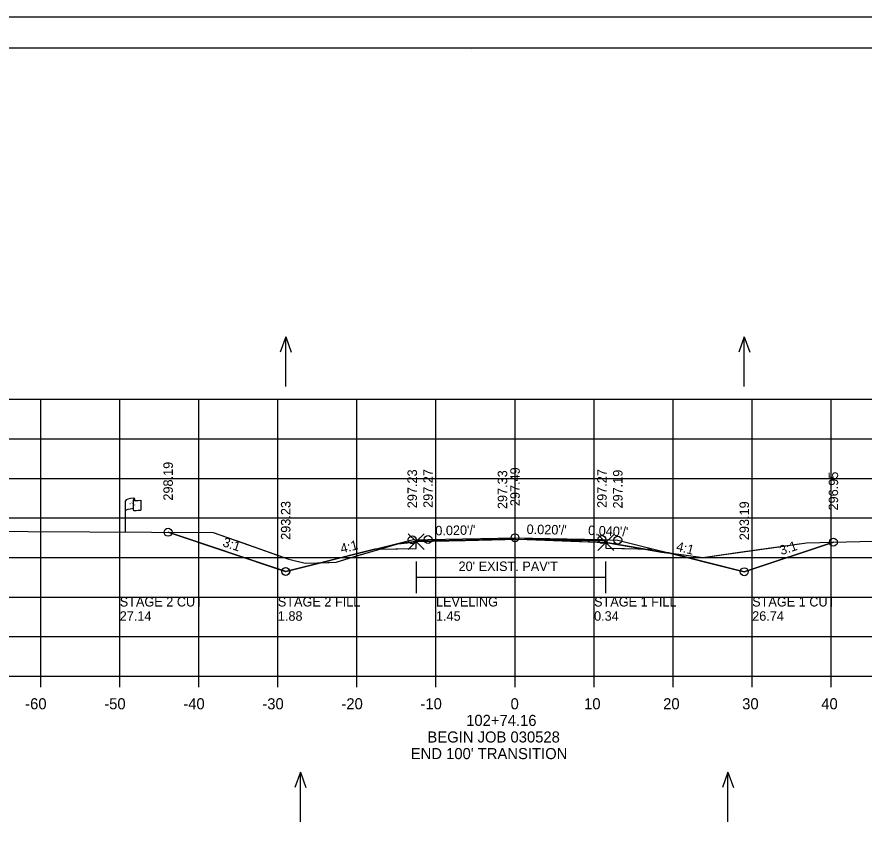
# Model space of a CAD drawing. Extents: x 1370843 to 1371177, y 380307 to 382654.
# Drawn here: x 1370950.7 to 1371057.9, y 380418.2 to 380520.8 of the extents above; entities that cross this region are included whole.
import ezdxf

# ---------------------------------------------------------------- set-up
doc = ezdxf.new("R2010")
doc.units = 0
for name, color, linetype in [('R_Alt Surface', 7, 'Continuous'), ('R_Axis', 7, 'Continuous'), ('R_Axis Annot', 7, 'Continuous'), ('R_Border', 7, 'Continuous'), ('R_Exist Surface', 7, 'Continuous'), ('R_Exist Surface Annot', 7, 'Continuous'), ('R_Fin Surface', 7, 'Continuous'), ('R_Fin Surface Annot', 7, 'Continuous'), ('R_Grid', 7, 'Continuous'), ('R_No Plot', 7, 'Continuous'), ('R_ROW', 7, 'Continuous'), ('R_Water Annot', 7, 'Continuous'), ('R_Xsect Elev', 7, 'Continuous')]:
    doc.layers.add(name, color=color, linetype=linetype)

msp = doc.modelspace()

# ---------------------------------------------------------------- linework, layer by layer
at = {"layer": 'R_Alt Surface'}
msp.add_lwpolyline([(1370996, 380453.5), (1371001.2, 380453.6), (1371001.2, 380454.52), (1371013.71, 380454.77), (1371025.19, 380454.54), (1371025.19, 380453.62), (1371031.25, 380453.5)], dxfattribs=at)
at = {"layer": 'R_Axis'}
for p, q in [((1370868.71, 380437.45), (1371158.71, 380437.45)), ((1370953.71, 380436.05), (1370953.71, 380437.45)), ((1370963.71, 380436.05), (1370963.71, 380437.45)), ((1370973.71, 380436.05), (1370973.71, 380437.45)), ((1370983.71, 380436.05), (1370983.71, 380437.45)), ((1370993.71, 380436.05), (1370993.71, 380437.45)), ((1371003.71, 380436.05), (1371003.71, 380437.45)), ((1371013.71, 380436.05), (1371013.71, 380437.45)), ((1371023.71, 380436.05), (1371023.71, 380437.45)), ((1371033.71, 380436.05), (1371033.71, 380437.45)), ((1371043.71, 380436.05), (1371043.71, 380437.45)), ((1371053.71, 380436.05), (1371053.71, 380437.45))]:
    msp.add_line(p, q, dxfattribs=at)
at = {"layer": 'R_Border'}
for p, q in [((1370855.71, 380516.91), (1371171.89, 380516.91)), ((1371008.23, 380516.65), (1371008.23, 380516.65)), ((1371008.23, 380516.65), (1371008.23, 380516.65))]:
    msp.add_line(p, q, dxfattribs=at)
at = {"layer": 'R_Exist Surface'}
msp.add_lwpolyline([(1370937.97, 380455.88), (1370952.11, 380455.75), (1370975.55, 380455.6), (1370979.39, 380454.25), (1370985.11, 380452.24), (1370985.6, 380452.11), (1370987.18, 380451.73), (1370990.21, 380451.81), (1370991.09, 380451.85), (1370993.15, 380452.5), (1370998.87, 380454.17), (1371000.11, 380454.32), (1371001.2, 380454.46), (1371007.41, 380454.61), (1371014.14, 380454.78), (1371019.68, 380454.56), (1371025.19, 380454.34), (1371028.42, 380453.78), (1371032.26, 380453.13), (1371035.35, 380452.76), (1371037.45, 380452.43), (1371042.42, 380453.16), (1371050.56, 380454.31), (1371065.7, 380454.68)], dxfattribs=at)
at = {"layer": 'R_Exist Surface Annot'}
for p, q in [((1371001.23, 380447.94), (1371001.23, 380451.94)), ((1371025.19, 380447.94), (1371025.19, 380451.94)), ((1371001.23, 380449.94), (1371025.19, 380449.94))]:
    msp.add_line(p, q, dxfattribs=at)
at = {"layer": 'R_Fin Surface'}
msp.add_lwpolyline([(1370969.83, 380455.64), (1370984.7, 380450.68), (1370984.71, 380450.68), (1370996, 380453.5), (1371000.71, 380454.68), (1371002.71, 380454.72), (1371013.71, 380454.94), (1371024.71, 380454.72), (1371026.71, 380454.64), (1371031.25, 380453.5), (1371042.71, 380450.64), (1371053.98, 380454.39)], dxfattribs=at)
at = {"layer": 'R_Grid'}
for p, q in [((1370868.71, 380472.45), (1371158.71, 380472.45)), ((1370953.71, 380437.45), (1370953.71, 380472.45)), ((1370963.71, 380437.45), (1370963.71, 380472.45)), ((1370973.71, 380437.45), (1370973.71, 380472.45)), ((1370983.71, 380437.45), (1370983.71, 380472.45)), ((1370993.71, 380437.45), (1370993.71, 380472.45)), ((1371003.71, 380437.45), (1371003.71, 380472.45)), ((1371013.71, 380437.45), (1371013.71, 380472.45)), ((1371023.71, 380437.45), (1371023.71, 380472.45)), ((1371033.71, 380437.45), (1371033.71, 380472.45)), ((1371043.71, 380437.45), (1371043.71, 380472.45)), ((1371053.71, 380437.45), (1371053.71, 380472.45)), ((1370868.71, 380467.45), (1371158.71, 380467.45)), ((1370868.71, 380462.45), (1371158.71, 380462.45)), ((1370868.71, 380457.45), (1371158.71, 380457.45)), ((1370868.71, 380452.45), (1371158.71, 380452.45)), ((1370868.71, 380447.45), (1371158.71, 380447.45)), ((1370868.71, 380442.45), (1371158.71, 380442.45)), ((1370868.71, 380437.45), (1371158.71, 380437.45))]:
    msp.add_line(p, q, dxfattribs=at)
at = {"layer": 'R_No Plot'}
msp.add_line((1370843.31, 380520.8), (1371176.64, 380520.8), dxfattribs=at)
for points in [[(1370843.3, 380520.8), (1371176.64, 380520.8), (1371176.64, 380307.47), (1370843.3, 380307.47)], [(1371089.63, 380516.91), (1371089.63, 380507.03), (1371125.36, 380507.03), (1371125.36, 380504.11), (1371148.56, 380504.11), (1371148.56, 380479.78), (1371171.89, 380479.78), (1371171.89, 380311.45), (1370855.71, 380311.45), (1370855.71, 380516.91)], [(1370984.71, 380450.68), (1370969.83, 380455.64), (1370975.55, 380455.6), (1370985.11, 380452.24), (1370987.18, 380451.73), (1370989.12, 380451.78)], [(1370996.63, 380453.51), (1371001.2, 380453.6), (1371001.2, 380454.46), (1370998.87, 380454.17)], [(1371001.2, 380454.52), (1371001.2, 380454.46), (1371013.8, 380454.77), (1371013.71, 380454.77)], [(1371014.92, 380454.75), (1371025.19, 380454.34), (1371025.19, 380454.54)], [(1371025.19, 380454.34), (1371025.19, 380453.62), (1371029.9, 380453.53)], [(1371033.16, 380453.02), (1371035.35, 380452.76), (1371037.45, 380452.43), (1371046.49, 380453.73), (1371050.56, 380454.31), (1371053.98, 380454.39), (1371042.71, 380450.64)], [(1370989.12, 380451.78), (1370990, 380451.81), (1370991.09, 380451.85), (1370993, 380452.45), (1370993.82, 380452.69), (1370996.63, 380453.51), (1370996, 380453.5)], [(1371029.9, 380453.53), (1371031.25, 380453.5), (1371033.16, 380453.02), (1371032.26, 380453.13)]]:
    msp.add_lwpolyline(points, close=True, dxfattribs=at)
for points in [[(1371001.2, 380454.46), (1371000.2, 380455.46), (1371001.2, 380454.46), (1371000.2, 380453.46), (1371001.2, 380454.46), (1371002.2, 380453.46), (1371001.2, 380454.46), (1371002.2, 380455.46)], [(1371025.19, 380454.34), (1371024.19, 380455.34), (1371025.19, 380454.34), (1371024.19, 380453.34), (1371025.19, 380454.34), (1371026.19, 380453.34), (1371025.19, 380454.34), (1371026.19, 380455.34)]]:
    msp.add_lwpolyline(points, dxfattribs=at)
for centre in [(1370969.83, 380455.64), (1371000.71, 380454.68), (1371002.71, 380454.72), (1371013.71, 380454.94), (1371024.71, 380454.72), (1371026.71, 380454.64), (1371053.98, 380454.39), (1370984.7, 380450.68), (1370984.71, 380450.68), (1371042.71, 380450.64)]:
    msp.add_circle(centre, 0.5, dxfattribs=at)
at = {"layer": 'R_ROW'}
for p, q in [((1370964.43, 380455.67), (1370964.43, 380459.62)), ((1370965.42, 380459.72), (1370965.42, 380459.7)), ((1370965.42, 380459.7), (1370965.42, 380458.48)), ((1370965.59, 380459.87), (1370965.59, 380459.63)), ((1370966.36, 380459.68), (1370966.36, 380458.44))]:
    msp.add_line(p, q, dxfattribs=at)
for centre, radius, start, end in [((1370965.5, 380459.72), 0.078, 88.6458, 274.2828), ((1370965.51, 380459.87), 0.0783, 263.0712, 93.9564), ((1370965.5, 380458.48), 0.0783, 180, 273.9564)]:
    msp.add_arc(centre, radius, start, end, dxfattribs=at)
for centre, major_axis, ratio, start_param, end_param in [((1370966.01, 380459.66), (-1.58, -0.04), 0.19887, 5.030368, 6.283185), ((1370966.72, 380459.78), (-1.23, -0.13), 0.052933, 0.159456, 1.268315), ((1370966.01, 380458.35), (-1.58, -0.04), 0.19887, 5.083035, 6.194897), ((1370966.72, 380458.54), (-1.23, -0.13), 0.052933, 0.159456, 1.268315)]:
    msp.add_ellipse(centre, major_axis=major_axis, ratio=ratio, start_param=start_param, end_param=end_param, dxfattribs=at)
at = {"layer": 'R_Water Annot'}
for p, q in [((1370984.71, 380480.35), (1370984.01, 380478.43)), ((1370984.71, 380474.06), (1370984.71, 380480.35)), ((1370984.71, 380480.35), (1370985.41, 380478.43)), ((1371042.71, 380480.35), (1371042.01, 380478.43)), ((1371042.71, 380474.06), (1371042.71, 380480.35)), ((1371042.71, 380480.35), (1371043.41, 380478.43)), ((1370986.57, 380425.3), (1370985.87, 380423.38)), ((1370986.57, 380419.02), (1370986.57, 380425.3)), ((1370986.57, 380425.3), (1370987.27, 380423.38)), ((1371040.65, 380425.3), (1371039.95, 380423.38)), ((1371040.65, 380419.02), (1371040.65, 380425.3)), ((1371040.65, 380425.3), (1371041.35, 380423.38))]:
    msp.add_line(p, q, dxfattribs=at)

# ---------------------------------------------------------------- texts
at = {"layer": 'R_Axis Annot'}
for s, p in [('-60', (1370951.75, 380433.25)), ('-50', (1370961.75, 380433.25)), ('-40', (1370971.75, 380433.25)), ('-30', (1370981.75, 380433.25)), ('-20', (1370991.75, 380433.25)), ('-10', (1371001.75, 380433.25)), ('0', (1371013.15, 380433.25)), ('10', (1371022.45, 380433.25)), ('20', (1371032.45, 380433.25)), ('30', (1371042.45, 380433.25)), ('40', (1371052.45, 380433.25)), ('102+74.16', (1371007.53, 380431.15)), ('BEGIN JOB 030528', (1371002.63, 380429.05)), ("END 100' TRANSITION", (1371000.52, 380426.95))]:
    msp.add_text(s, height=1.4, dxfattribs=at).set_placement(p)
at = {"layer": 'R_Exist Surface Annot'}
msp.add_text("20' EXIST. PAV'T", height=1.2, dxfattribs=at).set_placement((1371006.57, 380450.74))
at = {"layer": 'R_Fin Surface Annot'}
for s, rotation, p in [('298.19', 90, (1370970.43, 380459.64)), ('297.27', 90, (1371003.31, 380458.72)), ('297.49', 90, (1371014.31, 380458.94)), ('297.27', 90, (1371025.31, 380458.72)), ('297.23', 90, (1371001.31, 380458.68)), ('297.19', 90, (1371027.31, 380458.64)), ('296.95', 90, (1371054.58, 380458.39)), ('293.23', 90, (1370985.3, 380454.68)), ('293.23', 90, (1370985.31, 380454.68)), ('293.19', 90, (1371043.31, 380454.64)), ("0.020'/'", 1.1458, (1371003.64, 380455.24)), ("0.020'/'", 358.8542, (1371015.17, 380455.43)), ("0.040'/'", 357.7094, (1371022.94, 380455.3)), ('3:1', 341.5651, (1370976.63, 380453.9)), ('4:1', 14.0362, (1370991.78, 380452.96)), ('4:1', 345.9638, (1371034.02, 380453.32)), ('3:1', 18.4349, (1371047.4, 380452.73))]:
    msp.add_text(s, height=1.2, rotation=rotation, dxfattribs=at).set_placement(p)
at = {"layer": 'R_No Plot'}
for s, p in [('STAGE 2 CUT', (1370963.71, 380446.25)), ('STAGE 2 FILL', (1370983.71, 380446.25)), ('LEVELING', (1371003.71, 380446.25)), ('STAGE 1 FILL', (1371023.71, 380446.25)), ('STAGE 1 CUT', (1371043.71, 380446.25)), ('27.14', (1370963.71, 380444.45)), ('1.88', (1370983.71, 380444.45)), ('1.45', (1371003.71, 380444.45)), ('0.34', (1371023.71, 380444.45)), ('26.74', (1371043.71, 380444.45))]:
    msp.add_text(s, height=1.2, dxfattribs=at).set_placement(p)
at = {"layer": 'R_ROW'}
for s, height, rotation, p in [('R ', 0.2, 9.9884, (1370964.95, 380459.12)), (' O', 0.2, 9.9884, (1370965.09, 380459.17)), ('DWB 11-9-07', 0.001, 90, (1370965.59, 380459.63)), ('W', 0.2, 351.1788, (1370965.42, 380459)), ('DWB 11-9-07', 0.001, 5.0717, (1370966.35, 380458.44)), ('DWB 11-9-07', 0.001, 90, (1370964.43, 380455.67))]:
    msp.add_text(s, height=height, rotation=rotation, dxfattribs=at).set_placement(p)
at = {"layer": 'R_Xsect Elev'}
msp.add_text('297.33', height=1.2, rotation=90, dxfattribs=at).set_placement((1371012.72, 380458.57))

doc.saveas('drawing.dxf')
